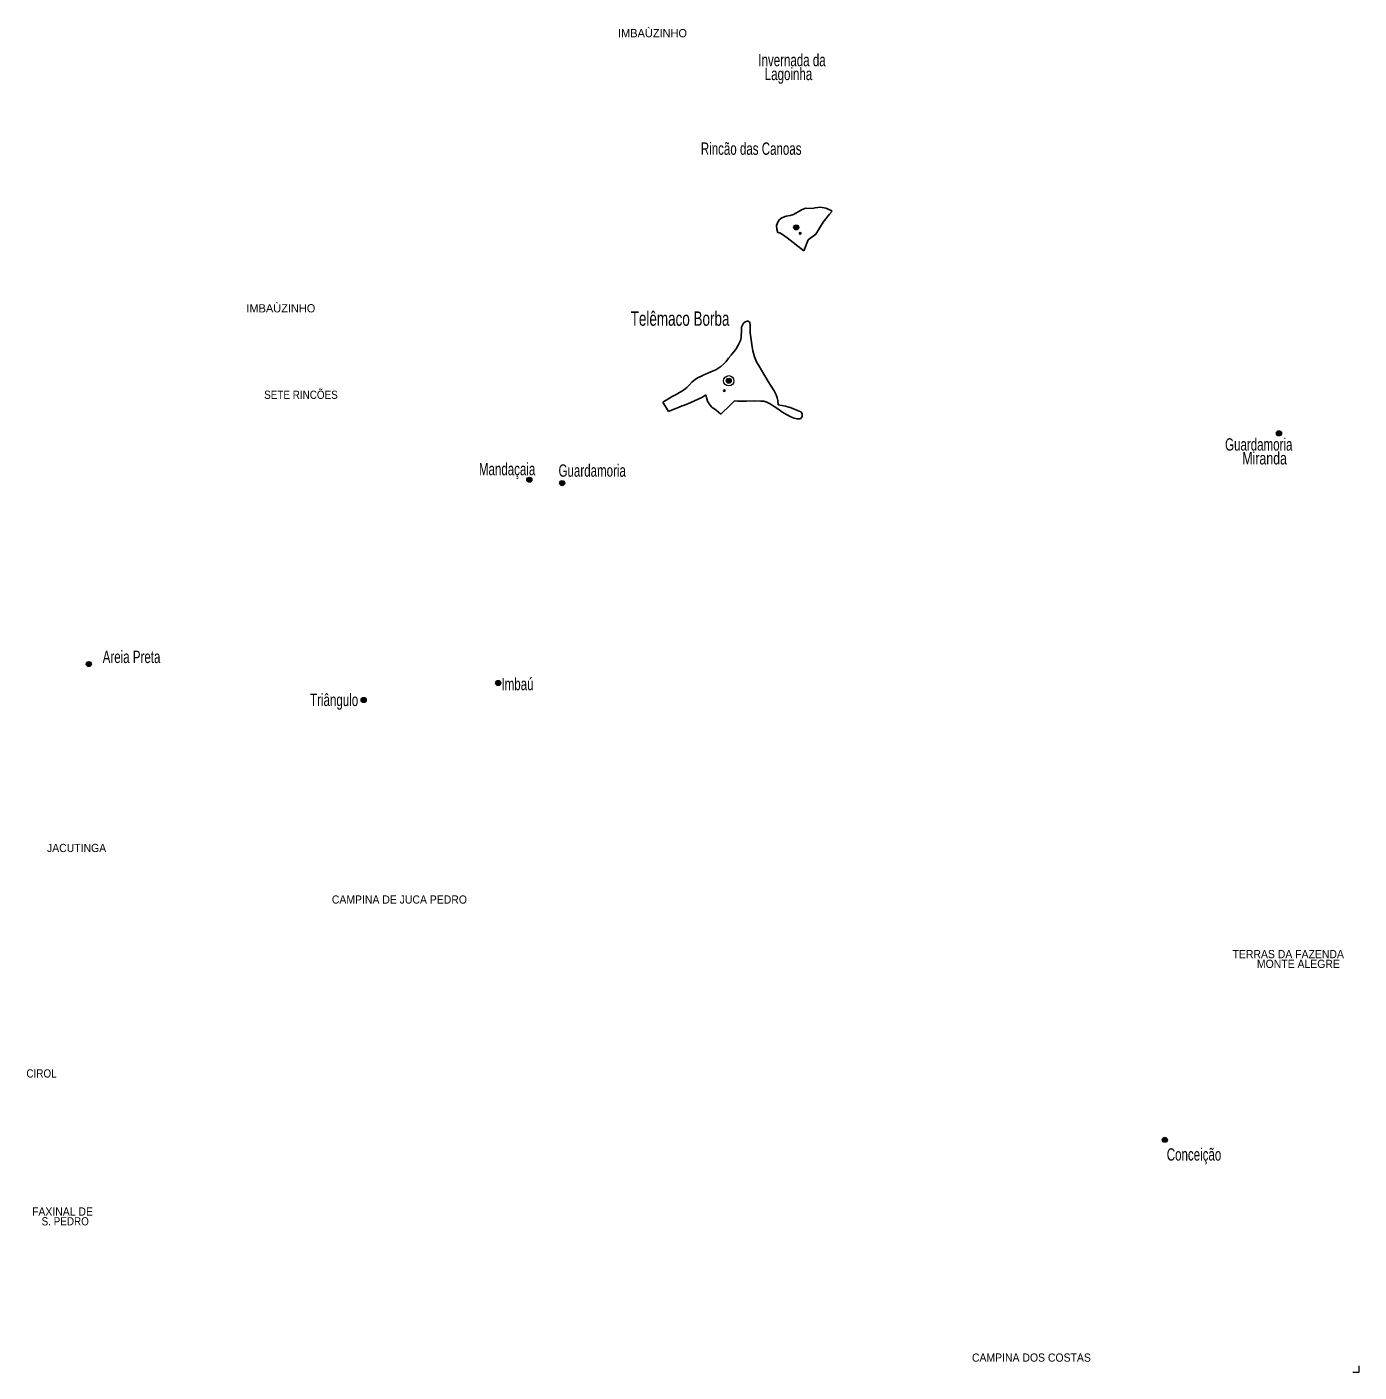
# Model space of a CAD drawing. Extents: x 500 to 550.9, y 7290.3 to 7345.7.
# Drawn here: x 524.7 to 550.65, y 7290.29 to 7316.49 of the extents above; entities that cross this region are included whole.
import ezdxf
from ezdxf.enums import TextEntityAlignment as Align

# ---------------------------------------------------------------- set-up
doc = ezdxf.new("R2010")
doc.units = 0
doc.header["$LTSCALE"] = 0.064
doc.header["$PDMODE"] = 32
doc.header["$PDSIZE"] = 0.032
for name, color, linetype, lineweight in [('41', 7, 'Continuous', 25), ('42', 7, 'Continuous', 25), ('50', 7, 'Continuous', 13), ('52', 7, 'Continuous', 13), ('63', 7, 'Continuous', 13)]:
    doc.layers.add(name, color=color, linetype=linetype, lineweight=lineweight)
doc.layers.add('56', color=7, linetype='Continuous')
doc.layers.add('61', color=7, linetype='Continuous')

msp = doc.modelspace()

# ---------------------------------------------------------------- hatches: boundary and pattern name
at = {"layer": '50'}
msp.add_hatch(color=256, dxfattribs=at).paths.add_polyline_path([(538.4205, 7309.5961, 1), (538.3205, 7309.5961, 1)])
at = {"layer": '52'}
for points in [[(539.73449, 7312.58276, 1), (539.63449, 7312.58276, 1)], [(549.13499, 7308.57176, 1), (549.03499, 7308.57176, 1)], [(534.53789, 7307.66856, 1), (534.43789, 7307.66856, 1)], [(535.17689, 7307.60196, 1), (535.07689, 7307.60196, 1)], [(525.95979, 7304.07826, 1), (525.85979, 7304.07826, 1)], [(533.93129, 7303.70836, 1), (533.83129, 7303.70836, 1)], [(531.31239, 7303.37776, 1), (531.21239, 7303.37776, 1)], [(546.91139, 7294.81056, 1), (546.81139, 7294.81056, 1)]]:
    msp.add_hatch(color=256, dxfattribs=at).paths.add_polyline_path(points)

# ---------------------------------------------------------------- linework, layer by layer
at = {"layer": '41'}
for points in [[(539.3296, 7312.4794), (539.3059, 7312.5481), (539.3039, 7312.6184), (539.3254, 7312.6829), (539.3508, 7312.7299), (539.4075, 7312.7709), (539.4896, 7312.8002), (539.5678, 7312.8158), (539.6303, 7312.8315), (539.7241, 7312.8843), (539.8004, 7312.9331), (539.8727, 7312.9566), (539.9987, 7312.9486)], [(540.3873, 7312.899), (540.3334, 7312.8397), (540.2083, 7312.6832), (540.0676, 7312.4486), (539.9202, 7312.3407)]]:
    msp.add_lwpolyline(points, dxfattribs=at)
for p in [(539.7627, 7312.4661), (538.2843, 7309.4026)]:
    msp.add_point(p, dxfattribs=at)
at = {"layer": '42'}
for p, q in [((539.8321, 7312.1245), (539.9202, 7312.3407)), ((538.6154, 7310.4401), (538.62, 7310.5859)), ((537.0884, 7309.1818), (537.2002, 7308.9953)), ((538.1243, 7309.0227), (538.2147, 7308.9438))]:
    msp.add_line(p, q, dxfattribs=at)
for points in [[(539.9987, 7312.9486), (540.0523, 7312.9646), (540.1578, 7312.9749), (540.2585, 7312.9582), (540.3657, 7312.9094), (540.3873, 7312.899)], [(539.3296, 7312.4794), (539.3396, 7312.4827), (539.3764, 7312.4694), (539.4657, 7312.4136), (539.5081, 7312.3794), (539.8321, 7312.1245)], [(538.7852, 7310.5831), (538.7908, 7310.6403), (538.7861, 7310.6874), (538.7806, 7310.7225), (538.7732, 7310.7409), (538.7668, 7310.7465), (538.7511, 7310.7538), (538.7308, 7310.7566), (538.6874, 7310.7446), (538.6588, 7310.716), (538.6366, 7310.6763), (538.6209, 7310.6394), (538.62, 7310.5859)], [(538.6154, 7310.4401), (538.5979, 7310.3828), (538.5803, 7310.3376), (538.5545, 7310.2859), (538.5148, 7310.2176), (538.4677, 7310.1613), (538.4299, 7310.1149), (538.4151, 7310.0967), (538.3644, 7310.0358), (538.3182, 7309.9712), (538.2767, 7309.9223)], [(538.7852, 7310.5831), (538.788, 7310.5296), (538.7988, 7310.4382)], [(538.7988, 7310.4382), (538.8295, 7310.2546), (538.8397, 7310.178), (538.8701, 7310.0626), (538.9144, 7309.962), (538.9615, 7309.8799), (539.0538, 7309.7248), (539.1405, 7309.5818), (539.2531, 7309.4009), (539.293, 7309.3207), (539.3138, 7309.265), (539.3247, 7309.2137), (539.3345, 7309.1297)], [(538.2767, 7309.9223), (538.2192, 7309.8716), (538.1198, 7309.8053)], [(537.9055, 7309.7169), (537.8755, 7309.7043), (537.8512, 7309.6942), (537.7652, 7309.6554), (537.7172, 7309.6175), (537.6531, 7309.5661), (537.5983, 7309.5113), (537.5545, 7309.4641), (537.4871, 7309.4102)], [(538.1198, 7309.8053), (538.0204, 7309.7711), (537.9055, 7309.7169)], [(537.4871, 7309.4102), (537.3455, 7309.3259), (537.2698, 7309.2867)], [(537.2698, 7309.2867), (537.2511, 7309.277), (537.0884, 7309.1818)], [(537.5081, 7309.1221), (537.4655, 7309.105), (537.4059, 7309.0832)], [(537.9273, 7309.3231), (537.8585, 7309.2778), (537.8461, 7309.2696), (537.6333, 7309.1723), (537.5081, 7309.1221)], [(537.9273, 7309.3231), (537.9352, 7309.2696), (537.9552, 7309.197), (537.9878, 7309.1432), (538.0009, 7309.1286)], [(538.0009, 7309.1286), (538.0441, 7309.0807), (538.1243, 7309.0227)], [(538.4842, 7309.2053), (538.4094, 7309.1333), (538.2147, 7308.9438)], [(538.4842, 7309.2053), (538.5431, 7309.1993), (538.7144, 7309.1982), (538.8658, 7309.2038), (538.9956, 7309.1997)], [(538.9956, 7309.1997), (539.054, 7309.1952), (539.1151, 7309.181), (539.1795, 7309.1472), (539.2548, 7309.0926), (539.3236, 7309.0511), (539.3262, 7309.0492)], [(539.7803, 7308.8711), (539.7874, 7308.8798), (539.7983, 7308.9027), (539.8015, 7308.9235), (539.7994, 7308.9464), (539.7917, 7308.9671), (539.7743, 7308.9879), (539.7088, 7309.0195), (539.5866, 7309.0653), (539.4731, 7309.1013), (539.4065, 7309.1155), (539.3345, 7309.1297)], [(537.4059, 7309.0832), (537.3372, 7309.0579), (537.258, 7309.0237), (537.2002, 7308.9953)], [(539.3262, 7309.0492), (539.4021, 7308.9933), (539.496, 7308.9387), (539.5811, 7308.8951), (539.6455, 7308.8689), (539.699, 7308.8536), (539.7273, 7308.8525), (539.7524, 7308.8525), (539.7732, 7308.8624), (539.7803, 7308.8711)]]:
    msp.add_lwpolyline(points, dxfattribs=at)
at = {"layer": '50'}
for radius in [0.1, 0.05]:
    msp.add_circle((538.3705, 7309.5961), radius, dxfattribs=at)
at = {"layer": '52'}
for centre in [(539.68449, 7312.58276), (549.08499, 7308.57176), (534.48789, 7307.66856), (535.12689, 7307.60196), (525.90979, 7304.07826), (533.88129, 7303.70836), (531.26239, 7303.37776), (546.86139, 7294.81056)]:
    msp.add_circle(centre, 0.05, dxfattribs=at)
at = {"layer": '63'}
msp.add_lwpolyline([(550.5219, 7290.2873), (550.6451, 7290.2873), (550.6451, 7290.4087)], dxfattribs=at)

# ---------------------------------------------------------------- texts
at = {"layer": '56'}
for p in [(536.8865, 7316.286), (529.6492, 7310.927)]:
    msp.add_text('IMBAÙZINHO', height=0.16, dxfattribs=at).set_placement(p, align=Align.CENTER)
for s, width, p in [('SETE RINCÕES', 0.9, (530.04095, 7309.2429)), ('JACUTINGA', 0.95, (525.67155, 7300.416)), ('CAMPINA DE JUCA PEDRO', 0.95, (531.95785, 7299.4117)), ('TERRAS DA FAZENDA', 0.95, (549.26555, 7298.3485)), ('       MONTE ALEGRE', 0.95, (549.2656, 7298.1585)), ('CIROL', 0.9, (524.9888, 7296.0244)), ('FAXINAL DE', 0.95, (525.3971, 7293.3344)), ('  S. PEDRO', 0.9, (525.3971, 7293.1444)), ('CAMPINA DOS COSTAS', 0.95, (544.2643, 7290.4899))]:
    msp.add_text(s, height=0.16, dxfattribs=dict(at, width=width)).set_placement(p, align=Align.CENTER)
at = {"layer": '61'}
for s, width, p in [('Invernada da', 0.7, (538.9472, 7315.7211)), ('  Lagoinha', 0.7, (538.9472, 7315.4511)), ('Guardamoria', 0.7, (548.036, 7308.2352)), ('     Miranda', 0.75, (548.036, 7307.9652)), ('Guardamoria', 0.7, (535.0567, 7307.7264)), ('Areia Preta', 0.7, (526.1802, 7304.0976)), ('Imbaú', 0.7, (533.9451, 7303.5689)), ('Conceição', 0.7, (546.9001, 7294.4067))]:
    msp.add_text(s, height=0.24, dxfattribs=dict(at, width=width)).set_placement(p)
at = {"layer": '61', "width": 0.7}
for s, height, p in [('Rincão das Canoas', 0.24, (539.7876, 7313.9963)), ('Telêmaco Borba', 0.28, (538.3845, 7310.6666)), ('Mandaçaia', 0.24, (534.6046, 7307.7548)), ('Triângulo', 0.24, (531.155, 7303.2598))]:
    msp.add_text(s, height=height, dxfattribs=at).set_placement(p, align=Align.RIGHT)

doc.saveas('drawing.dxf')
